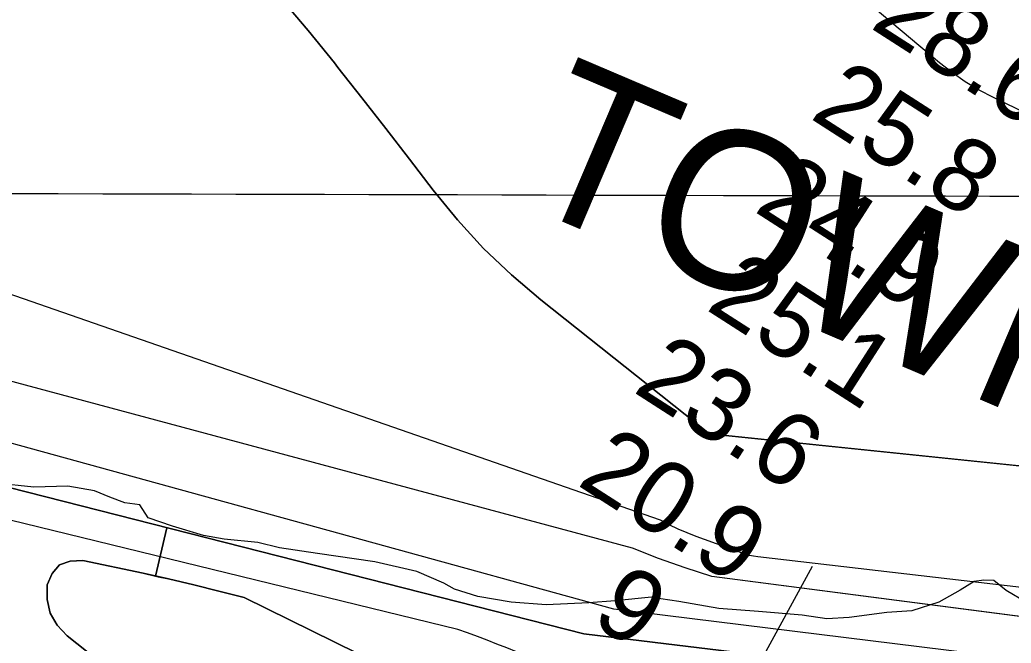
# Model space of a CAD drawing. Extents: x 3161615 to 3199515, y 867541 to 892976.
# Drawn here: x 3183730 to 3184643, y 878603 to 879177 of the extents above; entities that cross this region are included whole.
import ezdxf

# ---------------------------------------------------------------- set-up
doc = ezdxf.new("R2010")
doc.units = 0
for name, color, linetype in [('V-GRID-MAJR', 7, 'Continuous'), ('V-RIVR-EDGE', 7, 'Continuous'), ('V-RIVR-IDEN', 7, 'Continuous'), ('V-RIVR-RANG', 7, 'Continuous'), ('V-RRAP-RVMT-IDEN', 7, 'Continuous'), ('V-TOPO-DPTH', 7, 'Continuous'), ('V-TOPO-MINR', 7, 'Continuous'), ('V-TOPO-WATR', 7, 'Continuous')]:
    doc.layers.add(name, color=color, linetype=linetype)

msp = doc.modelspace()

# ---------------------------------------------------------------- linework, layer by layer
at = {"layer": 'V-GRID-MAJR'}
msp.add_spline([(3165838.644, 879070.158), (3171065.6580000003, 879053.813), (3176292.6750000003, 879038.2270000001), (3181519.694, 879023.402), (3186746.716, 879009.337), (3191973.739, 878996.033), (3197200.764, 878983.488), (3197200.765, 878983.488)], degree=3, dxfattribs=at)
at = {"layer": 'V-RIVR-EDGE'}
msp.add_lwpolyline([(3184656.974595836, 878640.6747820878), (3184638.403688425, 878651.6888376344), (3184626.9811521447, 878660.777715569), (3184617.9217534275, 878661.2769922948), (3184608.857638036, 878659.8687789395), (3184595.96203412, 878651.7937836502), (3184576.3831399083, 878640.8740616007), (3184551.5657229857, 878632.8285455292), (3184528.672304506, 878631.4545280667), (3184493.848818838, 878626.7718821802), (3184473.33976296, 878625.391968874), (3184450.4581361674, 878628.7866766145), (3184410.4090986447, 878632.2238344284), (3184373.6969895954, 878635.1758655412), (3184336.9931347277, 878641.4660042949), (3184320.308492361, 878643.8916378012), (3184311.7283245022, 878645.3434803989), (3184278.3389939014, 878642.087914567), (3184254.013778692, 878640.2405620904), (3184214.905515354, 878638.4297638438), (3184182.4840798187, 878640.8943099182), (3184151.977209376, 878646.2153744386), (3184130.5344543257, 878652.9446523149), (3184120.533102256, 878658.2150125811), (3184095.762852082, 878669.2443973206), (3184057.1574029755, 878677.9236153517), (3184004.243419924, 878685.6844634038), (3183969.4446968, 878691.0161404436), (3183949.427842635, 878695.8343907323), (3183918.438203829, 878698.7722718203), (3183899.3715571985, 878702.157546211), (3183870.780431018, 878710.812001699), (3183848.3862892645, 878718.4973829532), (3183840.785808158, 878730.4380626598), (3183826.9612217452, 878732.3797486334), (3183813.1448895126, 878737.6595422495), (3183798.852863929, 878743.4173875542), (3183774.542977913, 878747.7693778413), (3183743.0670332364, 878746.8934579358), (3183708.263593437, 878750.3176448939)], dxfattribs=at)
at = {"layer": 'V-RIVR-RANG'}
msp.add_line((3183922.7562000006, 877691.4420999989), (3184460.0887000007, 878674.129099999), dxfattribs=at)
at = {"layer": 'V-TOPO-DPTH'}
for points in [[(3183383.6255490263, 880245.3684840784), (3183769.0418592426, 879411.9228313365), (3183778.787662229, 879401.3671745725), (3183788.623931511, 879390.8939786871), (3183919.6555376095, 879253.1523640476), (3183945.667786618, 879225.0333363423), (3183971.1423610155, 879196.4484188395), (3183995.8104234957, 879167.1646666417), (3184019.940811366, 879137.4150246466), (3184023.1737148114, 879133.3137130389), (3184045.213752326, 879105.2104976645), (3184067.1605724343, 879077.0350423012), (3184088.9675664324, 879048.7512269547), (3184110.6813430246, 879020.39517162), (3184133.282977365, 878992.9237446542), (3184157.1452897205, 878966.6880350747), (3184182.8986190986, 878942.3059015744), (3184209.912626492, 878919.1594854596), (3184365.1802415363, 878795.8880473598), (3184900.4239182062, 878740.5359215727), (3184883.3047360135, 878597.4410033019)], [(3183865.506115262, 878709.428854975), (3183372.849847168, 878834.8355776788), (3183360.358108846, 878842.5375766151), (3183347.873590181, 878850.2512727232), (3183335.393884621, 878857.9727669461), (3183221.151293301, 878915.7147544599)], [(3186857.987428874, 878310.4006473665), (3186121.587410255, 878417.7982438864), (3185298.599713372, 878541.3402296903), (3185288.2889970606, 878544.7410168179), (3184367.4775580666, 878664.5648101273), (3184342.8152662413, 878672.4023551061), (3184318.429542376, 878680.9730698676), (3184294.458670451, 878690.6435393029), (3183495.1305291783, 878905.2467260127)], [(3184883.3047360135, 878597.4410033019), (3184367.4775580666, 878664.5648101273), (3184342.8152662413, 878672.4023551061), (3184318.429542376, 878680.9730698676), (3184294.458670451, 878690.6435393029), (3183495.1305291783, 878905.2467260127)], [(3183372.849847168, 878834.8355776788), (3184249.570273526, 878611.664489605), (3185230.8329057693, 878492.6025050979), (3185239.5889615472, 878489.9185044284), (3185248.3665675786, 878487.3086996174), (3185257.1764989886, 878484.8101885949), (3185266.0079806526, 878482.3858734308), (3186088.3919671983, 878334.1032975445), (3186116.9719442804, 878329.7201433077), (3186145.491880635, 878324.9143121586)], [(3184146.4127295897, 878327.8380489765), (3184126.0131929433, 878338.3115003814), (3184106.1699994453, 878349.6822995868), (3184087.16132067, 878362.3991204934), (3184068.7089850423, 878376.0132892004), (3183773.7889948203, 878609.8285210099), (3183764.761234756, 878619.8148607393), (3183758.256994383, 878630.7938620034), (3183755.5380335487, 878643.2618555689), (3183755.3425924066, 878656.7225106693), (3183760.127324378, 878667.3596378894), (3183766.8715389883, 878675.1564646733), (3183776.5549775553, 878678.692840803), (3183788.197898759, 878679.3889164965), (3183843.7690162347, 878667.4237620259), (3183855.273961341, 878664.8631988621), (3183865.506115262, 878709.428854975)], [(3183868.6918123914, 878708.617928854), (3183865.506115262, 878709.428854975), (3183855.273961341, 878664.8631988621), (3183857.6949213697, 878664.3243852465), (3183867.0813911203, 878662.235314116), (3183890.342454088, 878656.8326768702), (3183913.5265491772, 878651.10875562), (3183936.659332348, 878645.1706450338), (3184186.6065439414, 878522.222251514), (3184248.9785296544, 878479.1657162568), (3184282.446902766, 878422.1001908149), (3184336.879298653, 878298.6185323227), (3184339.9819446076, 878286.8990336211), (3184338.405226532, 878277.5302031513), (3184329.8022996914, 878267.3921345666), (3184308.724975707, 878265.8653730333), (3184229.600789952, 878293.2191795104), (3184146.4127295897, 878327.8380489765)], [(3186145.491880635, 878324.9143121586), (3186116.9719442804, 878329.7201433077), (3186088.3919671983, 878334.1032975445), (3185266.0079806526, 878482.3858734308), (3185257.1764989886, 878484.8101885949), (3185248.3665675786, 878487.3086996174), (3185239.5889615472, 878489.9185044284), (3185230.8329057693, 878492.6025050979), (3184249.570273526, 878611.664489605), (3183868.6918123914, 878708.617928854)], [(3184146.4127295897, 878327.8380489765), (3184126.0131929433, 878338.3115003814), (3184106.1699994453, 878349.6822995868), (3184087.16132067, 878362.3991204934), (3184068.7089850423, 878376.0132892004), (3183773.7889948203, 878609.8285210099), (3183764.761234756, 878619.8148607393), (3183758.256994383, 878630.7938620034), (3183755.5380335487, 878643.2618555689), (3183755.3425924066, 878656.7225106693), (3183760.127324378, 878667.3596378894), (3183766.8715389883, 878675.1564646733), (3183776.5549775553, 878678.692840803), (3183788.197898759, 878679.3889164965), (3183843.7690162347, 878667.4237620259), (3183867.0813911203, 878662.235314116), (3183890.342454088, 878656.8326768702), (3183913.5265491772, 878651.10875562), (3183936.659332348, 878645.1706450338), (3184022.9802118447, 878602.7096253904)]]:
    msp.add_lwpolyline(points, dxfattribs=at)
at = {"layer": 'V-TOPO-MINR'}
for points in [[(3186200.2118157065, 878610.9195077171), (3185383.5250675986, 878686.8742623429), (3185355.705240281, 878693.4530878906), (3184365.1802415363, 878795.8880473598), (3184209.912626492, 878919.1594854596), (3184182.8986190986, 878942.3059015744), (3184157.1452897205, 878966.6880350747), (3184133.282977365, 878992.9237446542), (3184110.6813430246, 879020.39517162), (3184088.9675664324, 879048.7512269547), (3184067.1605724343, 879077.0350423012), (3184045.213752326, 879105.2104976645), (3184023.1737148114, 879133.3137130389), (3184019.940811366, 879137.4150246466), (3183995.8104234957, 879167.1646666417), (3183971.1423610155, 879196.4484188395), (3183945.667786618, 879225.0333363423), (3183919.6555376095, 879253.1523640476), (3183788.623931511, 879390.8939786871), (3183778.787662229, 879401.3671745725), (3183769.0418592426, 879411.9228313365), (3183383.6255490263, 880245.3684840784)], [(3184691.2307680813, 879074.3752905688), (3184626.6191710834, 879105.4908512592), (3184613.501149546, 879112.4313163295), (3184600.7877959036, 879119.9968344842), (3184588.6814441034, 879128.4999322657), (3184576.979760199, 879137.6280831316), (3184497.019272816, 879205.0199327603)], [(3186226.2450040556, 878419.2293016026), (3185306.8407527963, 878580.0219622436), (3185300.3511631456, 878579.7135013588), (3185293.861181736, 878579.5726345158), (3185287.3706126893, 878579.6831587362), (3185280.8796518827, 878579.961276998), (3185274.460967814, 878580.680867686), (3185268.136901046, 878581.8115919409), (3185261.954760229, 878583.5590165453), (3184409.753244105, 878682.7317077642), (3184405.823570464, 878683.1284121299), (3184401.9636970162, 878683.9657210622), (3184398.150357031, 878685.0967663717), (3184353.0191594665, 878701.3209339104), (3184344.571946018, 878704.6084881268), (3184336.256141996, 878708.1812119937), (3184328.137452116, 878712.1816903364), (3184320.1501716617, 878716.46733833), (3183479.786941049, 879008.278451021)], [(3186147.2983375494, 878379.3295241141), (3186128.676513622, 878384.1360410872), (3185314.401796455, 878506.3831856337), (3184277.182839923, 878634.3805067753), (3183394.0893720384, 878877.4493847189)], [(3186145.491880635, 878324.9143121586), (3186116.9719442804, 878329.7201433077), (3186088.3919671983, 878334.1032975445), (3185266.0079806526, 878482.3858734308), (3185257.1764989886, 878484.8101885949), (3185248.3665675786, 878487.3086996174), (3185239.5889615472, 878489.9185044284), (3185230.8329057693, 878492.6025050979), (3184249.570273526, 878611.664489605), (3183372.849847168, 878834.8355776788)], [(3184248.048062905, 878570.7617867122), (3184232.838272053, 878576.6644537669), (3184217.6935068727, 878582.7389662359), (3184205.327160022, 878587.8207488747), (3184196.407203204, 878591.4655654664), (3184187.477691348, 878595.0866845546), (3184178.5338469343, 878598.6722573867), (3184169.580447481, 878602.2341327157), (3184160.6010079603, 878605.7277883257), (3184151.596411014, 878609.1542021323), (3184142.554077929, 878612.479753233), (3184133.4865874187, 878615.7380625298), (3183388.1043961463, 878797.7976993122)], [(3184186.6065439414, 878522.222251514), (3183936.659332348, 878645.1706450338), (3183913.5265491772, 878651.10875562), (3183890.342454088, 878656.8326768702), (3183867.0813911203, 878662.235314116), (3183843.7690162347, 878667.4237620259), (3183788.197898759, 878679.3889164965), (3183776.5549775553, 878678.692840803), (3183766.8715389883, 878675.1564646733), (3183760.127324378, 878667.3596378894), (3183755.3425924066, 878656.7225106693), (3183755.5380335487, 878643.2618555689), (3183758.256994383, 878630.7938620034), (3183764.761234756, 878619.8148607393), (3183773.7889948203, 878609.8285210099), (3184068.7089850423, 878376.0132892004)]]:
    msp.add_lwpolyline(points, dxfattribs=at)
at = {"layer": 'V-TOPO-WATR'}
msp.add_lwpolyline([(3186857.987428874, 878310.4006473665), (3186121.587410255, 878417.7982438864), (3185298.599713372, 878541.3402296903), (3185288.2889970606, 878544.7410168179), (3184367.4775580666, 878664.5648101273), (3184342.8152662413, 878672.4023551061), (3184318.429542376, 878680.9730698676), (3184294.458670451, 878690.6435393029), (3183495.1305291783, 878905.2467260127)], dxfattribs=at)

# ---------------------------------------------------------------- texts
at = {"layer": 'V-RIVR-IDEN'}
msp.add_text('TOWHEAD', height=144.99971200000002, rotation=336.92905133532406, dxfattribs=at).set_placement((3184183.362308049, 879011.0251871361))
at = {"layer": 'V-RIVR-RANG'}
for s, p in [('28.6', (3184511.872590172, 879170.4762057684)), ('25.8', (3184456.5148870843, 879087.1824448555)), ('24.9', (3184404.929342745, 879001.4645065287)), ('25.1', (3184360.6691653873, 878911.042753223)), ('23.6', (3184293.548085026, 878835.3036042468)), ('20.9', (3184241.9635406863, 878749.5856659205)), ('9', (3184254.522695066, 878622.673711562))]:
    msp.add_text(s, height=67, rotation=327.29083333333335, dxfattribs=at).set_placement(p)
at = {"layer": 'V-RRAP-RVMT-IDEN'}
msp.add_text('POINT', height=99.99980200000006, rotation=341.3901455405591, dxfattribs=at).set_placement((3183424.522188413, 878567.5297919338))

doc.saveas('drawing.dxf')
